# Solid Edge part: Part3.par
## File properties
Author: Deepak Maini
Template: Normal.par
Last saved by: CADCIM
Revision: 3
Application: Solid Edge
Accuracy: 0.99
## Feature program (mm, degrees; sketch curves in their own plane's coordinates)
sketch for "unnamed Protrusion 1" #1 plane through (0, 0, 0) normal (0, 0, 1) x-axis (1, 0, 0)
  line (-42.48, -13.536) -> (53.136, -13.536)
  arc centre (53.136, -1.872) radius 11.664 from (53.136, 9.792) to (53.136, -13.536) cw
  line (53.136, 9.792) -> (-42.48, 9.792)
  arc centre (-42.48, -1.872) radius 11.664 from (-42.48, 9.792) to (-42.48, -13.536) ccw
sketch for "unnamed Protrusion 1" #2 plane through (0, 0, 0) normal (0, 0, 1) x-axis (1, 0, 0)
  circle centre (-42.48, -1.872) radius 7
sketch for "unnamed Protrusion 1" #3 plane through (0, 0, 0) normal (0, 0, 1) x-axis (1, 0, 0)
  circle centre (53.136, -1.872) radius 7
extrude "unnamed Protrusion 1" add finite 13 along -normal
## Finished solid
Body 1: solid body, 8 faces, 16 edges, 8 vertices.
  Faces by surface: cylinder 4, plane 4
  Edges by curve: circle 8, line 8
Bounding box of the edges (mm): 118.944 x 23.328 x 13.000, from (-54.144, -13.536, -13) to (64.8, 9.792, 0).
Cylindrical faces by radius (mm): R7 x2, R11.664 x2
Planar faces by outward normal: +y 1, +z 1, -y 1, -z 1
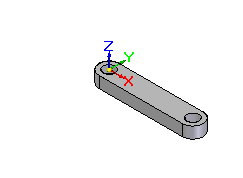
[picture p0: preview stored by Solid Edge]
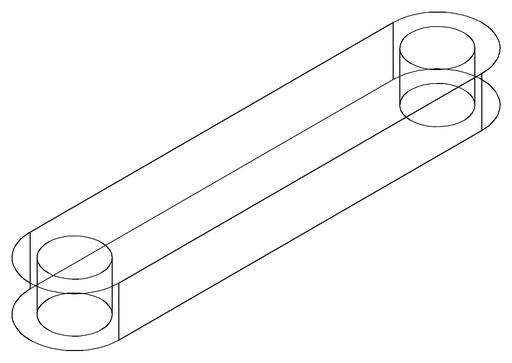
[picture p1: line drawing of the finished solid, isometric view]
